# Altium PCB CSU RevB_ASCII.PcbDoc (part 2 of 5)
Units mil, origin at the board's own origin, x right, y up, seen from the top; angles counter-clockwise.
Board outline 5905.51 x 4330.71 mil, 8 copper layers (Top Layer, InternalPlane1, MidLayer1, InternalPlane2, MidLayer2, InternalPlane3, MidLayer3, Bottom Layer); 265 components, 387 nets, 1910 pads, 1151 vias.
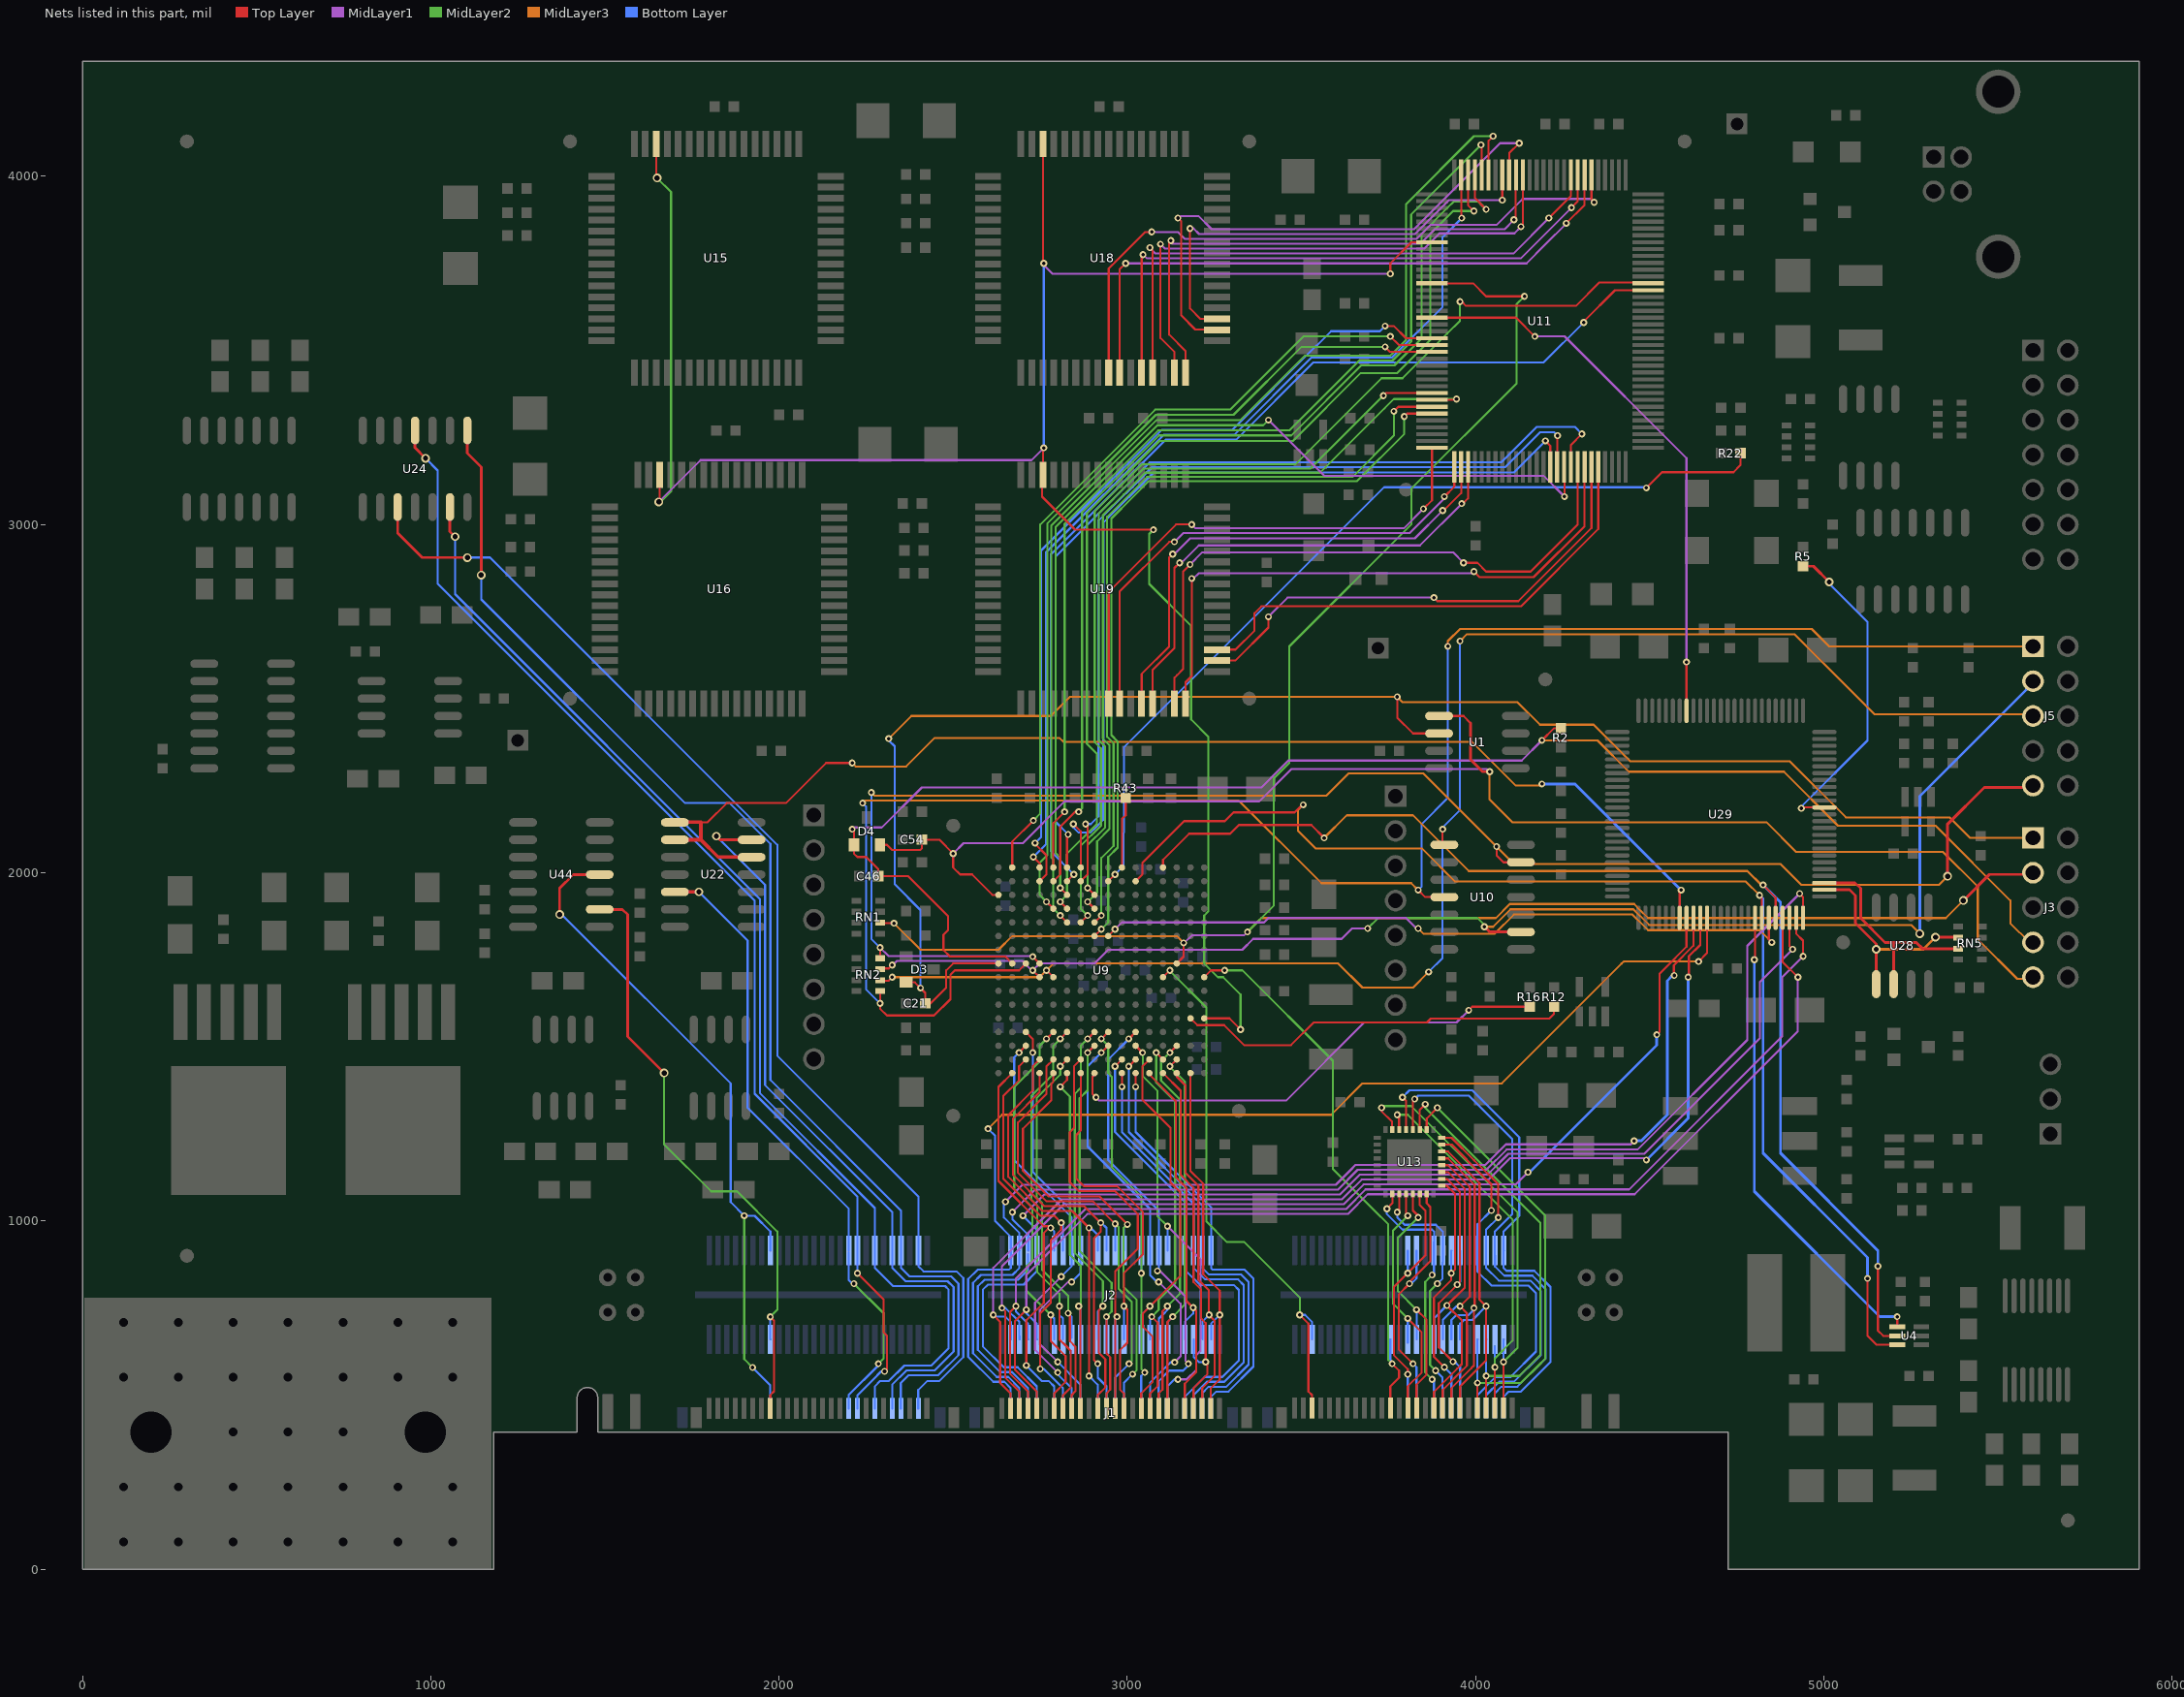
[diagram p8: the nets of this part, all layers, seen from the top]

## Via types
v1: diameter 20, hole 10, Top Layer to Bottom Layer, 647 vias
v2: diameter 25, hole 15, Top Layer to Bottom Layer, 352 vias
v3: diameter 20, hole 10, Top Layer to Bottom Layer, tented top, 151 vias
v4: diameter 20, hole 10, Top Layer to Bottom Layer, tented bottom, 1 vias

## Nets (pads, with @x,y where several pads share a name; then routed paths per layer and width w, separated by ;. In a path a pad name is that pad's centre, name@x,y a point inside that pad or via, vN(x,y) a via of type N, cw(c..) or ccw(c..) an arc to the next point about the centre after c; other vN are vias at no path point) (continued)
A_INP_SEL_N: U22.5 U22.8 U22.9 U29.57 | length 3570.2
  Top Layer w6: 1775,2145 1795,2145 1850,2200 2020,2200 2135,2315 v1(2210,2315) ; U29.57@4585.67,1870.51 4585.67,1945.67 v1(4590,1950)
  Top Layer w10: U22.8@1695,2150 1700,2145 1775,2145 1775.43,2144.57 1775.43,2094.57 ; U22.9@1701.14,2094.57 1775.43,2094.57 ; U22.5@1915,2045 1825,2045 1775.43,2094.57
  Top Layer w20: U22.5@1915,2045 U22.5@1925,2045
  MidLayer3 w6: v1(2210,2315) 2220,2305 2365,2305 2447.28,2387.28 2805,2387.28 2816.28,2376 3989,2376 4013.37,2351.63 4115,2250 4190,2250 v1(4190,2255)
  Bottom Layer w8: v1(4190,2255) 4285,2255 v1(4590,1950)
A_INTERFACE_RESET_N: J1.141 J2.141 U44.2 | length 1808.8
  Top Layer w6: J1.141@1974.71,461.79 J1.141@1974.71,470 ; v1(1974.71,724.71) 1985.71,713.71 1985.71,511 1975,500.29 J1.141@1975,470
  Top Layer w8: U44.2@1484.96,1894.57 1550.43,1894.57 1565,1880 1565,1530 v2(1670,1425)
  MidLayer2 w6: v2(1670,1425) 1670,1220 1805,1085 1880,1085 1995,970 1995,745 v1(1974.71,724.71)
  Bottom Layer w6: v1(1974.71,724.71) 1974.71,660.33 J2.141@1975.2,659.84
A_SCLK: J1.108 J2.108 U24.3 | length 3504.7
  Top Layer w8: U24.3@905,3050 905,2975 975,2905 v2(1105,2905)
  Bottom Layer w6: v2(1105,2905) 1170,2905 1995,2080 1995,1475 2400.2,1069.8 2400.2,869.8 2415,855 2510,855 2529,836 2529,609.2 2459.8,540 2425,540 2399.71,514.71 J1.108@2399.71,461.79
A_SIMO: J1.112 J2.112 U24.8 | length 3655.8
  Top Layer w8: U24.8@1105,3270 1105,3205 1145,3165 v2(1145,2855)
  Bottom Layer w6: v2(1145,2855) 1145,2785 1730,2200 1858.03,2200 1888.62,2169.41 1975,2083.03 1975,1405 2350.2,1029.8 2350.2,865 2374.2,841 2494,841 2515,820 2515,615 2457,557 2371.8,557 2349.71,534.91 J1.112@2349.71,461.79
A_SOMI: J1.114 J2.114 U22.6 | length 2222
  Top Layer w8: v2(1820,2105) 1830.43,2094.57 U22.6@1921.14,2094.57
  Bottom Layer w6: v2(1820,2105) 1960,1965 1960,1390 2325.2,1024.8 2325.2,865 2363.2,827 2484,827 2501,810 2501,625 2447,571 2366,571 2324.71,529.71 J1.114@2324.71,461.79
A_TCK: J5.1 RN2.1 U9.H3 U10.11 | length 5428.7
  Top Layer w6: RN2.1@2290.01,1660 2290.01,1635 v1(2290,1625) 2290.01,1609.99 2310,1590 2445,1590 2492,1637 2492,1707 2504.72,1719.72 2689.06,1719.72 U9.H3@2708.74,1739.41 ; v1(3835,1950) 3855,1930 U10.11@3910,1930
  MidLayer3 w6: v1(2240,2200) 2247,2207 3320,2207 3557,1970 3815,1970 v1(3835,1950) ; v1(3920,2650) 3920,2665 3955,2700 4965,2700 5015,2650 J5.1@5600,2650
  Bottom Layer w6: v1(2240,2200) 2249.7,2190.3 2249.7,1665.3 v1(2290,1625) ; v1(3835,1950) 3845,1960 3845,2140 3920,2215 v1(3920,2650)
A_TDI: J5.9 RN2.4 U9.H4 U10.6 | length 4774.8
  Top Layer w6: RN2.4@2290.01,1754.49 v1@2290.01,1784.99 ; v3(2728.43,1759.09) U9.H4@2748.11,1739.41 ; v1(4060,2075) 4060,2050 4080,2030 U10.6@4130,2030 U10.6@4135,2030
  Top Layer w8: v2(5355,1990) 5355,2140 5460,2245 5595,2245 J5.9@5600,2250
  MidLayer1 w6: v1(2290,1785) 2313.91,1761.09 2726.43,1761.09 v3(2728.43,1759.09)
  MidLayer3 w6: v1(2265,2230) 2274,2221 3571,2221 3635,2285 3850,2285 v1(4060,2075) 4110,2025 4875,2025 4935,1965 5330,1965 v2(5355,1990)
  Bottom Layer w6: v1(2265,2230) 2265,1810 v1(2290,1785)
A_TDO: J5.3 RN2.3 U9.J4 U10.2 | length 4126.9
  Top Layer w6: RN2.3@2290.01,1725 2315,1725 v1(2325,1735) ; v3(2728.43,1719.72) U9.J4@2748.11,1700.04
  Top Layer w8: v1(4025,1845) 4040,1830 U10.2@4130,1830
  MidLayer1 w6: v1@2326.97,1735 2339.07,1747.09 2697.91,1747.09 2725.28,1719.72 v3(2728.43,1719.72) ; v3@2729.72,1719.72 2729.72,1721.02 2748.11,1739.41 2905.59,1739.41 2944.96,1778.78 3330,1778.78 3361.22,1810 3615,1810 3645,1840 v1(3690,1840)
  MidLayer2 w6: v1(3690,1840) 3720,1870 4005,1870 4025,1850 v1(4025,1845)
  MidLayer3 w6: v1(4025,1845) 4050,1845 4100,1895 4453.03,1895 4498.03,1850 5250,1850 v2(5275,1825)
  Bottom Layer w8: v2(5275,1825) 5275,2220 5595,2540 5595,2545 J5.3@5600,2550
A_TMS: J5.5 RN2.2 U9.J5 U10.8 | length 4455.7
  Top Layer w6: RN2.2@2290,1690 2315,1690 v1(2325,1700) ; v3(2767.8,1719.72) U9.J5@2787.48,1700.04 ; v1(3905,2125) 3905,2085 U10.8@3910,2080
  MidLayer3 w6: v1(2325,1700) 2459.96,1700 2460,1700.04 2748.11,1700.04 v3(2767.8,1719.72) 2787.48,1739.41 3605.59,1739.41 3675,1670 3820,1670 v1(3865,1715) ; v1(3955,2665) 3975,2685 4915,2685 5145,2455 5595,2455 J5.5@5600,2460
  Bottom Layer w6: v1(3865,1715) 3905,1755 3905,2130 3955,2180 v1(3955,2665)
ADC_1_DAT0: J1.55 J2.55 U9.T15 | length 1088.2
  Top Layer w6: U9.T15@3181.18,1424.45 3181.18,1143.82 3218,1107 3218,847 3265,800 3265,545 3239.86,519.86 J1.55@3239.86,461.79
  Bottom Layer w6: J2.55@3240.35,659.84 3240.35,705.35 v1(3265,730)
ADC_1_DAT1: J1.57 J2.57 U9.T14 | length 1101.2
  Top Layer w6: U9.T14@3141.81,1424.45 3141.81,1414.37 3167.18,1389 3167.18,1138.02 3204,1101.2 3204,831 3234.02,800.98 3234.02,730 3251,713.02 3251,556 3215,520 3215,461.93 J1.57@3214.86,461.79
  Bottom Layer w6: J2.57@3215.35,659.84 3215.35,710.35 v1(3235,730)
ADC_1_DAT2: J1.59 J2.59 U9.T13 | length 1128
  Top Layer w6: U9.T13@3102.44,1424.45 3153.18,1373.71 3153.18,1132.02 3190,1095.2 3190,825 3211.86,803.14 3211.86,720 3225,706.86 v1(3225,595) ; J1.59@3189.86,461.79 3189.86,519.86 3230,560 3230,595 v1@3225,600
  Bottom Layer w6: J2.59@3190.35,659.84 3190.35,609.65 3205,595 v1(3225,595)
ADC_1_DAT3: J1.61 J2.61 U9.T12 | length 1133.1
  Top Layer w6: U9.T12@3063.07,1424.45 3063.07,1420.11 3139.18,1344 3139.18,1125.82 3170,1095 3170,770 3197.86,742.14 3197.86,566 3164.86,533 J1.61@3164.86,461.79
  Bottom Layer w6: J2.61@3165.35,659.84 3165.35,710.58 3189,734.22 v1(3189,751)
ADC_1_DAT4: J1.65 J2.65 U9.R14 | length 1120.9
  Top Layer w6: J1.65@3114.86,461.79 3114.86,709.86 v1(3130,725) ; v3(3122.13,1444.13) U9.R14@3141.81,1463.82
  MidLayer2 w6: v3(3122.13,1444.13) 3122.13,1442.87 3165,1400 3165,760 v1(3130,725)
  Bottom Layer w6: J2.65@3115.35,659.84 3115,659.49 3115,710 v1(3130,725)
ADC_1_DAT5: J1.67 J2.67 U9.P14 | length 1213.4
  Top Layer w6: J1.67@3089.86,461.79 3089.86,505 3100.86,516 3100.86,740.86 v1(3115,755) ; v3(3122.13,1483.5) U9.P14@3141.81,1503.19
  MidLayer2 w6: v1(3115,755) 3151,791 3151,1348.76 3096.76,1403 3096.76,1458.13 v3(3122.13,1483.5)
  Bottom Layer w6: J2.67@3090.35,659.84 3090.35,719.83 3103.15,732.63 ; 3103.03,732.51 3115,744.48 v1(3115,755)
ADC_1_DAT6: J1.69 J2.69 U9.R13 | length 1183.2
  Top Layer w6: J1.69@3064.86,461.79 3064.86,504 3086.86,526 3086.86,708.14 v1(3070,725) ; v3(3082.76,1483.5) U9.R13@3102.44,1463.82
  MidLayer2 w6: v1(3070,725) 3090,745 3090,774 3137,821 3137,1342.96 3082.76,1397.2 v3(3082.76,1483.5)
  Bottom Layer w6: J2.69@3065.35,659.84 3065,660.2 3065,715 3070,720 v1(3070,725)
ADC_1_DAT7: J1.71 J2.71 U9.R12 | length 1219.6
  Top Layer w6: J1.71@3039.86,461.79 3039.86,504.86 3072.86,537.86 3072.86,667.14 3045,695 3045,735 3151.48,841.48 3151.48,1083.52 3124,1111 3124,1267 3043.39,1347.61 3043.39,1444.13 U9.R12@3063.07,1463.82
  Bottom Layer w6: J2.71@3040,670 3040,730 v1(3065,755)
ADC_2_DAT0: J1.56 J2.56 U9.T11 | length 1227.8
  Top Layer w6: v1(3023.7,1385.08) U9.T11@3023.7,1424.45
  Bottom Layer w6: v1(3023.7,1385.08) 3023.7,1255.7 3240.35,1039.04 J2.56@3240.35,914.96 3240.35,864.65 3245,860 3337,860 3362,835 3362,582 3290,510 3255,510 3239.86,494.86 J1.56@3239.86,461.79
ADC_2_DAT1: J1.58 J2.58 U9.R11 | length 1291.7
  Top Layer w6: v3(3004.02,1444.13) U9.R11@3023.7,1463.82
  Bottom Layer w6: v3(3004.02,1444.13) 3004.02,1424.45 3004.02,1255.58 3215.35,1044.24 3215.35,932.32 3215.35,865 3234.35,846 3327,846 3348,825 3348,587.8 3284.2,524 3233.6,524 3214.86,505.27 J1.58@3214.86,461.79
ADC_2_DAT2: J1.60 J2.60 U9.T10 | length 1252.3
  Top Layer w6: v1(2984.33,1385.08) U9.T10@2984.33,1424.45
  Bottom Layer w6: v1(2984.33,1385.08) 2984.33,1255.47 3030.17,1209.62 3190.35,1049.44 J2.60@3190.35,914.96 3190.35,865 3223.35,832 3318,832 3334,816 3334,593.6 3278.4,538 3227.8,538 3189.86,500.06 J1.60@3189.86,461.79
ADC_2_DAT3: J1.62 J2.62 U9.R10 | length 1307.9
  Top Layer w6: v3(2964.65,1444.13) U9.R10@2984.33,1463.82
  Bottom Layer w6: v3(2964.65,1444.13) 2964.65,1255.35 3018.78,1201.22 3165,1055 3165,915.31 J2.62@3165.35,914.96 ; J1.62@3164.86,461.79 3164.86,494.86 3222,552 3272.6,552 3320,599.4 3320,802 3305.85,816.15 3208.85,816.15 3165,860 J2.62@3165,914.61
ADC_2_DAT4: J1.66 J2.66 U9.P11 | length 1248.5
  Top Layer w6: U9.P11@3023.7,1503.19 v3(3043.39,1483.5)
  MidLayer1 w6: v1(3115.35,985) 3210,890.35 3210,627 3198,615 3198,572.99 3170,545 v1(3145,545)
  MidLayer2 w6: v3(3043.39,1483.5) 3045,1481.89 3045,1415.16 3086,1374.16 3086,1014.35 v1(3115.35,985)
  Bottom Layer w6: J1.66@3114.86,461.79 3114.86,524.86 3135,545 v1(3145,545) ; J2.66@3115.35,914.96 v1(3115.35,985)
ADC_2_DAT5: J1.68 J2.68 U9.N11 | length 1275
  Top Layer w6: v3(3004.02,1522.87) U9.N11@3023.7,1542.56
  MidLayer1 w6: v1(3086.35,856.35) 3093.65,856.35 3166.85,783.15 3166.85,598.15 v1(3175,590)
  Bottom Layer w6: v3(3004.02,1522.87) 2944.96,1463.82 2944.96,1174.64 2977.72,1141.88 3090.35,1029.24 3090.35,932.32 3090.35,860.35 v1(3086.35,856.35) ; J1.68@3089.86,461.79 3089.86,539.86 3110.18,560.18 3120,570 3160,570 3175,585 v1(3175,590)
ADC_2_DAT6: J1.70 J2.70 U9.P9 | length 1228.5
  Top Layer w6: v3(2925.28,1483.5) U9.P9@2944.96,1503.19 ; v1(3135.86,594.14) v1@3140,590
  MidLayer1 w6: v1(3089.94,825) 3090,825 3142.81,772.19 3152.85,762.15 3152.85,611.12 v1(3135.86,594.14)
  Bottom Layer w6: v3(2925.28,1483.5) 2885.91,1444.13 2885.91,1213.89 2950.11,1149.69 3065.35,1034.44 3065.35,912.64 3065.35,844.65 3085,825 v1(3089.94,825) ; J1.70@3064.86,461.79 3064.86,495 3065,495.14 3065,535 3108.36,578.36 3124.14,594.14 v1(3135.86,594.14)
ADC_2_DAT7: J1.72 J2.72 U9.N9 | length 1209.7
  Top Layer w6: v3(2925.28,1522.87) U9.N9@2944.96,1542.56
  MidLayer2 w6: v3(2925.28,1522.87) 2944.96,1503.19 2944.96,1424.45 2955.13,1414.28 2955.13,1154.98 3040,1070.12 v1(3040,850) 3040.9,849.1 3040.9,574.1 v1(3050,565)
  Bottom Layer w6: J1.72@3039.86,461.79 3039.86,554.86 v1(3050,565) ; v1(3040,850) J2.72@3040,914.96
ADC_3_DAT0: J1.75 J2.75 U9.T7 | length 1237.5
  Top Layer w6: U9.T7@2866.22,1424.45 2866.22,1259.5 2854,1247.28 2854,1121 2875,1100 2970,1100 3045,1025 3045,905 2990,850 v1(2990,755) 3000,745 3000,650 2978.86,628.86 2978.86,516.14 2989.86,505.14 J1.75@2989.86,461.79
  Bottom Layer w6: J2.75@2990.35,659.84 v1@2990.35,754.65
ADC_3_DAT1: J1.77 J2.77 U9.R7 | length 1262.8
  Top Layer w6: U9.R7@2866.22,1463.82 2846.54,1444.13 2846.54,1266.54 2835,1255 2835,1111 2860,1086 2964,1086 3030,1020 3030,920 2964.86,854.86 J1.77@2964.86,461.79 ; 2964.86,735 2970,729.86 v1(2970,725)
  Bottom Layer w6: J2.77@2965.35,659.84 2965.35,720.35 v1(2970,725)
ADC_3_DAT2: J1.79 J2.79 U9.P8 | length 1177.7
  Top Layer w6: v3(2885.91,1483.5) U9.P8@2905.59,1503.19 ; J1.79@2939.86,461.79 2939.86,480 2940,480.14 2940,505.14 2950.86,516 2950.86,608.73 2940,619.6 v1(2940,725)
  MidLayer2 w6: v3(2885.91,1483.5) 2885.91,1375 2863,1352.09 2863,914.03 2955,822.03 2955,740 v1(2940,725)
  Bottom Layer w6: v1(2940,725) 2940.35,724.65 J2.79@2940.35,659.84
ADC_3_DAT3: J1.81 J2.81 U9.N8 | length 1260.9
  Top Layer w6: v3(2885.91,1522.87) U9.N8@2905.59,1542.56 ; J1.81@2914.86,461.79 2914.86,499.86 2936.86,521.86 2936.86,602.94 2918,621.8 2918,743 v1(2930,755)
  MidLayer2 w6: v3(2885.91,1522.87) 2866.22,1503.19 2866.22,1382.22 2849,1365 2849,908.23 2930,827.23 v1(2930,755)
  Bottom Layer w6: J2.81@2915.35,659.84 2915.35,740.35 v1(2930,755)
ADC_3_DAT4: J1.85 J2.85 U9.T6 | length 1097.7
  Top Layer w6: v1(2807.17,1385.08) 2826.85,1404.76 U9.T6@2826.85,1424.45 ; v1(2860,755) 2865,750 2865,510 ; J1.85@2864.86,461.79 2864.86,510
  MidLayer2 w6: v1(2807.17,1385.08) 2835,1357.24 2835,902.43 2866.22,871.21 2866.22,761.22 v1(2860,755)
  Bottom Layer w6: v1(2860,755) 2865,750 2865,660.2 J2.85@2865.35,659.84 J2.85@2865.35,660.2
ADC_3_DAT5: J1.87 J2.87 U9.R6 | length 1164.5
  Top Layer w6: v3(2807.17,1444.13) U9.R6@2826.85,1463.82 ; v1(2830,735) 2835,730 2835,655 2850.86,639.14 2850.86,510.86 2840,500 J1.87@2840,460 ; J1.87@2839.86,461.79 J1.87@2840,461.93
  MidLayer2 w6: v3(2807.17,1444.13) 2807.17,1420.59 2740,1353.42 2740,1066.6 2755,1051.6 2755,860 2830,785 v1(2830,735)
  Bottom Layer w6: v1(2830,735) 2840,725 J2.87@2840,665
ADC_3_DAT6: J1.89 J2.89 U9.N6 | length 1278.4
  Top Layer w6: v1(2805,755) 2805,660 2824.55,640.45 2836.86,628.14 2836.86,521 2814.86,499 J1.89@2814.86,461.79 ; v3(2807.17,1522.87) U9.N6@2826.85,1542.56
  MidLayer2 w6: v1(2805,755) 2805,790 2741,854 2741,1045.8 2725,1061.8 2725,1360 2787.48,1422.48 2787.48,1503.19 v3(2807.17,1522.87)
  Bottom Layer w6: v1(2805,755) 2805,730 2815.35,719.65 J2.89@2815.35,659.84 J2.89@2815,660.2
ADC_3_DAT7: J1.91 J2.91 U9.N5 | length 1290.6
  Top Layer w6: v3(2767.8,1522.87) U9.N5@2787.48,1542.56 ; v1(2780,730) 2780,655 2822.86,612.14 2822.86,537.86 2789.86,504.86 J1.91@2789.86,461.79
  MidLayer2 w6: v3(2767.8,1522.87) 2748.11,1503.19 2748.11,1458.11 2675,1385 2675,1092 2727,1040 2727,886 2710.69,869.69 2710.69,799.31 v1(2780,730)
  Bottom Layer w6: v1(2780,730) 2790,720 J2.91@2790,660 ; J2.91@2790,660.2 J2.91@2790.35,659.84 J2.91@2790.35,660
ADC_4_DAT0: J1.76 J2.76 U9.T5 | length 1323.5
  Top Layer w6: U9.T5@2787.48,1424.45 2787.48,1399.68 2781.8,1394 2781.8,1346.8 2700,1265 2700,1143.99 2773.2,1070.8 2919.56,1070.8 3000,990.35 v1(3000,990)
  MidLayer2 w6: v1(3000,990) 2989,979 2989,811 3026.9,773.1 3026.9,571.9 v1(3015,560)
  Bottom Layer w6: J1.76@2989.86,461.79 2989.86,534.86 v1(3015,560) ; J2.76@2990.35,914.96 2990.35,980.35 v1(3000,990)
ADC_4_DAT1: J1.78 J2.78 U9.R5 | length 1354.2
  Top Layer w6: U9.R5@2787.48,1463.82 2767.8,1444.13 2767.8,1364.56 2686,1282.77 2686,1138.2 2767.4,1056.8 2900.2,1056.8 v1(2965,992)
  MidLayer2 w6: v1(2965,992) 2975,982 2975,805 3012.9,767.1 3012.9,597.9 v1(3005,590)
  Bottom Layer w6: J1.78@2964.86,461.79 2964.86,549.86 v1(3005,590) ; J2.78@2965,920 v1(2965,992) ; J2.78@2965.35,914.96 J2.78@2965.35,920
ADC_4_DAT2: J1.80 J2.80 U9.T4 | length 1266.3
  Top Layer w6: U9.T4@2748.11,1424.45 2748.11,1370.11 2672,1294 2672,1132.4 2761.6,1042.8 2875.74,1042.8 v1(2923.54,995) 2923.54,969.54 2904,950 2904,601 v1(2915,590)
  Bottom Layer w6: v1(2915,590) 2915,549.8 2940,524.8 J1.80@2940,470 ; v1@2925.35,995 2940.35,980 J2.80@2940.35,914.96
ADC_4_DAT3: J1.82 J2.82 U9.R4 | length 1274.2
  Top Layer w6: U9.R4@2748.11,1463.82 2728.43,1444.13 2728.43,1374.43 2658,1304 2658,1126.6 2755.8,1028.8 2841.2,1028.8 v1(2890,980) v1(2890,555)
  Bottom Layer w6: v1(2890,555) 2914.86,530.14 J1.82@2914.86,461.79 ; v1(2890,980) 2895,975 2900,975 2915.35,959.65 J2.82@2915.35,914.96
ADC_4_DAT4: J1.86 J2.86 U9.N3 | length 1247.7
  Top Layer w6: U9.N3@2708.74,1542.56 2728.43,1522.87 v3(2728.43,1483.5)
  MidLayer1 w6: v1(2800,595) 2749,646 2749,744 2830,825 v1(2840,825)
  Bottom Layer w6: v3(2728.43,1483.5) 2728.43,1141.18 2773.1,1096.5 2865.35,1004.25 2865.35,912.64 2865.35,850.35 v1(2840,825) ; v1(2800,595) 2864.86,530.14 J1.86@2864.86,461.79
ADC_4_DAT5: J1.88 J2.88 U9.P3 | length 1218.3
  Top Layer w6: v3(2689.06,1483.5) U9.P3@2708.74,1503.19
  MidLayer1 w6: v1(2800,565) 2735,630 2735,765 v4(2810,840)
  Bottom Layer w6: v3(2689.06,1483.5) 2688.5,1483.5 2675,1470 2675,1174.8 2714.75,1135.05 2840.35,1009.45 2840.35,912.64 2840.35,870.35 v4(2810,840) ; v1(2800,565) 2795,565 2839.86,520.14 J1.88@2839.86,461.79
ADC_4_DAT6: J1.90 J2.90 U9.R3 | length 1261
  Top Layer w6: U9.R3@2708.74,1463.82 2689.06,1444.13 2689.06,1404.06 2644,1359 2644,1120.8 2750,1014.8 2790.2,1014.8 v1(2810,995) 2810,975 2800,965 ; v1(2750,575) 2750,735.2 2780,765.2 2780,944.65 2800.18,964.82
  Bottom Layer w6: v1(2750,575) 2760,575 2815,520 2815,475.14 2814.86,475 J1.90@2814.86,461.79 ; v1(2810,995) 2815.35,989.65 J2.90@2815.35,914.96
ADC_4_DAT7: J1.92 J2.92 U9.T2 | length 1198.6
  Top Layer w6: U9.T2@2669.41,1424.41 U9.T2@2670,1425 ; U9.T2@2669.37,1424.45 2630,1385.08 2630,1115 2760,985 v1@2780,985 ; v1(2710,585) 2710,715 2760,765 2760,965 v1@2780,985 ; v1(2780,980) v1@2780,985
  Bottom Layer w6: v1(2710,585) 2755,540 2775,540 2790,525 J1.92@2790,465 ; v1(2780,980) 2790.35,969.65 J2.92@2790.35,914.96
ADDR0: U9.C8 U11.94 | length 2231.9
  Top Layer w6: v3(2885.91,1955.94) U9.C8@2905.59,1936.26 ; v1(3735,3370) 3742.48,3377.48 U11.94@3874.45,3377.48
  MidLayer2 w6: v3(2885.91,1955.94) 2885.91,2079.63 2936.33,2130.06 2936.33,2361.82 2918,2380.15 2918,3031.97 3006.75,3120.72 3046.6,3160.57 3525.57,3160.57 v1(3735,3370)
ADDR1: U9.D8 U11.95 | length 2396.7
  Top Layer w6: v3(2885.91,1916.57) U9.D8@2905.59,1896.89 ; U11.95@3874.45,3357.8 3942.8,3357.8 v1(3945,3360)
  MidLayer2 w6: v3(2885.91,1916.57) 2886.85,1916.57 2913.28,1943 2913.28,2090.03 2948.33,2125.09 2948.33,2366.79 2930,2385.12 2930,3027 2989.45,3086.45 3051.57,3148.57 3553.57,3148.57 3738.55,3333.55 3765,3360 v1(3945,3360)
ADDR2: U9.E8 U11.96 | length 2299.2
  Top Layer w6: U9.E8@2905.59,1857.52 v3(2925.28,1877.2) ; v1(3765,3325) 3778.11,3338.11 U11.96@3874.45,3338.11
  MidLayer2 w6: v3(2925.28,1877.2) 2925.28,2042.29 2960.33,2077.34 2960.33,2371.76 2942,2390.09 2942,3022.03 3056.54,3136.57 3646.57,3136.57 3765,3255 v1(3765,3325)
ADDR3: U9.F8 U11.97 | length 2308.7
  Top Layer w6: U9.F8@2905.59,1818.15 v3(2925.28,1837.83) ; v1(3795,3310) 3803.43,3318.43 U11.97@3874.45,3318.43
  MidLayer2 w6: v3(2925.28,1837.83) 2944.96,1857.52 2944.96,2045 2972.33,2072.37 2972.33,2376.73 2954,2395.06 2954,3017.06 3015.01,3078.07 3061.51,3124.57 3659.57,3124.57 3795,3260 v1(3795,3310)
ADDR4: U9.A7 U11.117 | length 2551
  Top Layer w6: v1(2845,2140) 2866.22,2118.78 U9.A7@2866.22,2015 ; v1(4200,3240) 4214.25,3225.75 U11.117@4214.25,3165.63
  Bottom Layer w6: v1(2845,2140) 2845,2130 2860,2115 2894,2115 2908.52,2129.52 2931.16,2152.16 2931.16,3005.27 3075,3149.11 4109.11,3149.11 v1(4200,3240)
ADDR5: U9.B7 U11.118 | length 2587.2
  Top Layer w6: U9.B7@2866.22,1975.63 2885.91,1995.32 2885.91,2134.09 v1(2880,2140) ; U11.118@4233.94,3165.63 4233.94,3253.94 v1(4235,3255)
  Bottom Layer w6: v1(2880,2140) 2895,2140 2917.16,2162.16 2917.16,3011.07 3070.8,3164.71 4084.71,3164.71 4185,3265 4225,3265 v1(4235,3255)
ADDR6: U9.C6 U11.119 | length 2835.7
  Top Layer w6: v3(2807.17,1955.94) U9.C6@2826.85,1936.26 ; U11.119@4253.62,3165.63 4255,3164.25 v1(4255,3080)
  MidLayer1 w6: v1(3405,3300) 3565,3140 4195,3140 v1(4255,3080)
  MidLayer2 w6: v3(2807.17,1955.94) 2807.17,2042.83 2794,2056 2794,2992.82 3086.18,3285 3390,3285 v1(3405,3300)
ADDR7: U9.A6 U11.120 | length 2689.6
  Top Layer w6: U9.A6@2826.85,2015 2826.85,2106.85 v1(2830,2110) ; U11.120@4273.31,3165.63 4273.31,3228.31 v1(4305,3260)
  Bottom Layer w6: v1(2830,2110) 2830,2110.35 2794.35,2146 2794.35,2908.06 3065,3178.71 4073.71,3178.71 4175,3280 4285,3280 v1(4305,3260)
ADDR14: U9.B6 U11.24 | length 3004.4
  Top Layer w6: U9.B6@2826.85,1975.63 v3(2846.53,1995.32) ; v1(4310,3580) 4310,3582.76 4400,3672.76 U11.24@4495,3672.76
  Bottom Layer w6: v3(2846.53,1995.32) 2780.35,2061.5 2780.35,2913.86 3110,3243.51 3312.4,3243.51 3533.89,3465 4195,3465 v1(4310,3580)
ADDR15: U9.E7 U11.25 | length 3126.4
  Top Layer w6: U9.E7@2866.22,1857.52 v3(2885.91,1877.2) ; v1(3955,3640) 3960,3640 3972.3,3627.7 4287.7,3627.7 4355,3695 U11.25@4490,3695
  MidLayer2 w6: v3(2885.91,1877.2) 2866.22,1896.89 2866.22,2076.92 2924.33,2135.03 2924.33,2356.85 2906,2375.18 2906,3036.94 3041.63,3172.57 3482.57,3172.57 3730,3420 3790,3420 3917.89,3547.89 3955,3585 v1(3955,3640)
ASD: C54.1 D4.2 J3.9 U1.5 U9.C1 | length 4323.5
  Top Layer w6: D4.2@2289.8,2080 2310,2080 2325,2065 2405,2065 2410,2070 C54.1@2410,2095.01 2459.99,2095.01 v1(2500,2055) 2500,2015 2520,1995 2553.97,1995 2612.71,1936.26 U9.C1@2630,1936.26 ; U1.5@3895,2450 3965,2450 3985,2430
  Top Layer w8: 3985,2430 3985,2325 4020,2290 v1(4040,2290)
  MidLayer1 w6: v1(2500,2055) 2529.75,2084.75 2699.75,2084.75 2820,2205 3378.94,2205 3471.94,2298 4032,2298 v1(4040,2290)
  MidLayer3 w6: v1(4040,2290) 4040,2210 4105,2145 4835,2145 4920,2060 5341.48,2060 5441.48,1960 5441.48,1808.52 5555,1695 5595,1695 J3.9@5600,1700
ASP_1_SEL_N: J1.95 J2.95 U29.72 | length 3369.2
  Top Layer w6: v1(2710,745) 2677,712 2677,573 2739.86,510.14 J1.95@2739.86,461.79 ; U29.72@4880.94,1870.51 4880.94,1744.06 v1(4925,1700)
  MidLayer1 w6: v1(2710,745) 2710,845 2885,1020 3633.25,1020 3690,1076.75 4456.75,1076.75 4925,1545 v1(4925,1700)
  Bottom Layer w6: v1(2710,745) 2710,735 2740,705 J2.95@2740,660 ; J2.95@2740.35,659.84 J2.95@2740.35,660
ASP_2_SEL_N: J1.96 J2.96 U29.73 | length 3497.3
  Top Layer w6: U29.73@4900.63,1870.51 4900.63,1789.37 v1(4910,1780)
  MidLayer1 w6: v1(2700,1015) 2761,1076 3610.06,1076 3622.2,1088.14 3666.8,1132.75 4033.59,1132.75 4093.84,1193 4483.92,1193 4815.92,1525 4815.92,1685.92 v1(4910,1780)
  Bottom Layer w6: v1(2700,1015) 2740.35,974.65 J2.96@2740.35,914.96 2740,914.61 2740,855 2702.2,817.2 2600,817.2 2585,802.2 2585,640 2645,580 2685,580 2739.86,525.14 J1.96@2739.86,461.79
ASP_3_SEL_N: J1.97 J2.97 U29.74 | length 3377.4
  Top Layer w6: v1(2680,755) 2663,738 2663,562 2714.86,510.14 J1.97@2714.86,461.79 ; U29.74@4920,1875 4920,1825 4940,1805 v1(4940,1760)
  MidLayer1 w6: v1(2680,755) 2680,834.8 2879.2,1034 3627.45,1034 3684.2,1090.75 4440.75,1090.75 4880,1530 4880,1700 v1(4940,1760)
  Bottom Layer w6: v1(2680,755) 2680,740 2715,705 2715,660.2 J2.97@2715.35,659.84
ASP_4_SEL_N: J1.98 J2.98 U29.75 | length 3638.3
  Top Layer w6: v1(4930,1940) 4940,1930 U29.75@4940,1870.51
  MidLayer1 w6: v1(2670,1025) 2735,1090 3604.26,1090 3661,1146.75 4030.62,1146.75 4088.87,1205 4465,1205 4780,1520 4780,1790 v1(4930,1940)
  Bottom Layer w6: v1(2670,1025) 2670,1005 2715.35,959.65 J2.98@2715.35,914.96 ; J1.98@2714.86,461.79 2714.86,520 2668.86,566 2635,566 2571,630 2571,812.2 2590,831.2 2686.2,831.2 2715,860 J2.98@2715,905
ATTN: U11.83 U29.18 | length 1624
  Top Layer w6: U11.83@3874.45,3594.02 4115.98,3594.02 v1(4170,3540) ; U29.18@4605,2465 U29.18@4605.35,2465 4605.35,2604.65 v1(4605,2605)
  MidLayer1 w6: v1(4170,3540) 4170.4,3540.4 4255,3540.4 4605,3190.4 v1(4605,2605)
B2_SCLK: U4.2 U9.A13 U29.71 | length 3514.5
  Top Layer w6: U9.A13@3102.44,2015 3102.44,2036.86 3177.58,2112 3294.88,2112 3319.88,2137 3528,2137 v1(3565,2100) ; v1(4825,1965) 4861.26,1928.74 U29.71@4861.26,1855 ; v1(5155,870) 5155,685 5170,670 U4.2@5210.55,670
  MidLayer3 w6: v1(3565,2100) 3630,2165 3820,2165 3980,2005 4780,2005 4820,1965 v1(4825,1965)
  Bottom Layer w8: v1(4825,1965) 4875,1915 4875,1195 5155,915 v1(5155,870)
B2_SIMO: U4.3 U9.B11 U29.69 | length 3642
  Top Layer w6: U9.B11@3023.7,1975.63 3043.39,1995.32 3043.39,2028.71 3162.67,2148 3279.97,2148 3304.97,2173 3480,2173 3502,2195 v1(3505,2195) ; v1(4815,1935) 4821.89,1928.11 U29.69@4821.89,1860 ; v1(5125,835) 5125,670 5150.59,644.41 U4.3@5210.55,644.41
  MidLayer3 w6: v1(3505,2195) 3490,2180 3490,2120 3540,2070 3845,2070 3940,1975 4775,1975 v1(4815,1935)
  Bottom Layer w8: v1(4815,1935) 4825,1925 4825,1195 5125,895 v1(5125,835)
B2_SOMI: U9.F9 U29.70 | length 2075.1
  Top Layer w6: U9.F9@2944.96,1818.15 v3(2964.65,1837.83) ; U29.70@4841.57,1870.51 4841.57,1808.43 v1(4850,1800)
  MidLayer1 w6: v3(2964.65,1837.83) 2984.33,1857.52 3392.52,1857.52 3405,1870 3800,1870 3830,1840 v1(3835,1840)
  MidLayer3 w6: v1(3835,1840) 3850,1825 4055,1825 4110,1880 4450,1880 4495,1835 4815,1835 v1(4850,1800)
B3_SCL: RN5.3 U28.6 U29.78 | length 632
  Top Layer w8: U29.78@5001.02,1970.91 5089.09,1970.91 5105,1955 5105,1870 5175,1800 5265,1800 5282.99,1782.01 RN5.3@5384.99,1782.01 ; U28.6@5200,1680 5200,1800
B3_SDA: RN5.2 U28.5 U29.77 | length 625.7
  Top Layer w8: U29.77@5001.02,1951.22 5073.78,1951.22 5090,1935 5090,1855 5150,1795 v2(5150,1780) U28.5@5150,1680 ; v2(5320,1815) 5383.5,1815 RN5.2@5384.99,1813.5
  MidLayer3 w8: v2(5150,1780) 5285,1780 v2(5320,1815)
B_DAT0: U11.44 U18.25 | length 1878
  Top Layer w6: U18.25@2946.46,3436 2946.46,3735 3051.46,3840 v1(3070,3840) ; U11.44@4332.36,4003.72 4332.36,3932.64 v1(4340,3925)
  MidLayer1 w6: v1(3070,3840) 3145,3840 3165,3820 3830,3820 3870,3860 4060,3860 4135,3935 4330,3935 v1(4340,3925)
B_DAT1: U11.45 U18.26 | length 1794.8
  Top Layer w6: U18.26@2977.95,3436 2977.95,3732.95 v1(2995,3750) ; v1(4260,3865) 4312.68,3917.68 U11.45@4312.68,4003.72
  MidLayer1 w6: v1(2995,3750) 4146,3750 4199.2,3803.2 4260,3864 v1(4260,3865)
B_DAT2: U11.46 U18.28 | length 1736.9
  Top Layer w6: U18.28@3040.94,3436 3040.94,3765 3045,3769.06 v1(3045,3775) ; v1(4275,3910) 4292.99,3927.99 U11.46@4292.99,4003.72
  MidLayer1 w6: v1(3045,3775) 3056,3764 4129,3764 v1(4275,3910)
B_DAT3: U11.47 U18.29 | length 1706.9
  Top Layer w6: v1(3065,3795) 3072.44,3787.56 U18.29@3072.44,3436 ; v1(4210,3880) 4273.31,3943.31 U11.47@4273.31,4003.72
  MidLayer1 w6: v1(3065,3795) 3065,3794 3081,3778 4108,3778 v1(4210,3880)
B_DAT4: U11.54 U18.31 | length 1604
  Top Layer w6: v1(3095,3805) 3095,3535.43 3135.43,3495 U18.31@3135.43,3436 ; v1(4130,3855) 4135.51,3860.51 U11.54@4135.51,4003.72 U11.54@4135,4003.2
  MidLayer1 w6: v1(3095,3805) 3108,3792 3852,3792 3896,3836 4111,3836 v1(4130,3855)
B_DAT5: U11.55 U18.32 | length 1552.7
  Top Layer w6: v1@3120,3815 3120,3545 3166.93,3498.07 U18.32@3166.93,3436 ; v1(4110,3875) 4115,3880 4115,4002.89 U11.55@4115.83,4003.72 U11.55@4115.83,4002.89
  MidLayer1 w6: v1@3120,3815 3129,3806 3841,3806 3883,3848 4083,3848 v1(4110,3875)
  other v1: 3125,3815
B_DAT6: U11.56 U18.34 | length 1610.3
  Top Layer w6: v1(3145,3880) 3155,3870 3155,3600 3195,3560 U18.34@3260,3560 ; U11.56@4095,4004.86 U11.56@4096.14,4003.72 4096.14,4066.14 v1(4125,4095)
  MidLayer1 w6: v1(3145,3880) 3150,3885 3205,3885 3242,3848 3823,3848 4039.9,4064.9 4070,4095 v1(4125,4095)
B_DAT7: U11.57 U18.35 | length 1335.9
  Top Layer w6: v1(3180,3850) 3180,3620 3209.45,3590.55 U18.35@3258,3590.55 ; v1(4076.46,3931.46) U11.57@4076.46,4003.72
  MidLayer1 w6: v1(3180,3850) 3190,3850 3206,3834 3825.97,3834 3923.43,3931.46 v1(4076.46,3931.46)
B_DAT8: U11.102 U19.25 | length 1517
  Top Layer w6: U19.25@2946.46,2486 2946.46,2806.46 3140,3000 v1(3185,3000) ; v1(3850,3045) 3874.45,3069.45 U11.102@3874.45,3220
  MidLayer1 w6: v1(3185,3000) 3196,2989 3794,2989 v1(3850,3045)
B_DAT9: U11.103 U19.26 | length 1467.1
  Top Layer w6: U19.26@2977.95,2486 2977.95,2807.95 3120,2950 v1(3135,2950) ; v1(3910,3080) 3938.66,3108.66 U11.103@3938.66,3165.63
  MidLayer1 w6: v1(3135,2950) 3160,2975 3810,2975 3910,3075 v1(3910,3080)
B_DAT10: U11.104 U19.28 | length 1457.3
  Top Layer w6: U19.28@3040.94,2486 3040.94,2570.94 3120,2650 3120,2905 v1(3130,2915) ; v1(3905,3040) 3908.35,3040 3958.35,3090 3958.35,3176.65 U11.104@3955.57,3179.43
  MidLayer1 w6: v1(3130,2915) 3135,2915 3180,2960 3825,2960 v1(3905,3040)
B_DAT11: U11.105 U19.29 | length 1431.4
  Top Layer w6: U19.29@3072.44,2486 3072.44,2582.64 3135,2645.2 3135,2875 v1(3150,2890) ; v1(3960,3060) 3963.03,3060 3978.03,3075 U11.105@3978.03,3165.63
  MidLayer1 w6: v1(3150,2890) 3155,2890 3205,2940 3840,2940 v1(3960,3060)
B_DAT12: U11.121 U19.31 | length 1789.3
  Top Layer w6: U19.31@3135.43,2486 3135.43,2560.43 3142.38,2567.38 3160,2585 3160,2865 v1(3180,2885) ; v1(3965,2890) 4005,2890 4030,2865 4157.99,2865 4292.99,3000 U11.121@4292.99,3165.63
  MidLayer1 w6: v1(3180,2885) 3215,2920 3935,2920 v1(3965,2890)
B_DAT13: U11.122 U19.32 | length 1743.4
  Top Layer w6: U19.32@3166.93,2486 3166.93,2546.93 3185,2565 v1(3185,2845) ; v1(3995,2865) 4011.34,2848.66 4166.33,2848.66 4312.68,2995 U11.122@4312.68,3165.63
  MidLayer1 w6: v1(3185,2845) 3190,2845 3205,2860 v1@4000,2860
B_DAT14: U11.123 U19.34 | length 1434.2
  Top Layer w6: U19.34@3258,2609.06 3310,2609.06 3405,2704.06 v1(3405,2735) ; v1(3880,2790) 3890,2780 4122.36,2780 4332.36,2990 U11.123@4332.36,3165.63
  MidLayer1 w6: v1(3405,2735) 3460,2790 v1(3880,2790)
B_DAT15: U11.124 U19.35 | length 1445.4
  Top Layer w6: U19.35@3258,2640.55 3310.55,2640.55 3365,2695 3365,2745 3385,2765 4130,2765 4352.05,2987.05 U11.124@4352.05,3165.63
B_INTERFACE_RESET_N: J1.142 J2.142 U44.4 | length 2028.5
  Top Layer w8: v2(1370,1880) 1370,1955 1409.57,1994.57 U44.4@1484.96,1994.57
  MidLayer2 w6: v1(1900,1015) 1900,603.35 v1(1924.18,579.18) v1@1925,580
  Bottom Layer w6: v2(1370,1880) 1376,1880 1861,1395 1861,1054 v1(1900,1015) 1930,1015 1975.2,969.8 J2.142@1975.2,914.96 ; v1(1924.18,579.18) 1974.71,528.65 J1.142@1974.71,461.79
B_SCLK: J1.118 J2.118 U24.6 | length 3421.8
  Top Layer w8: U24.6@1055,3055 1055,2980 v2(1070,2965)
  Bottom Layer w6: v2(1070,2965) 1070,2800 1945,1925 1945,1367.17 2275.2,1036.97 2275.2,865 2327.2,813 2477,813 2487,803 2487,635 2437,585 2360,585 2315.5,540.5 2290.5,540.5 2274.71,524.71 J1.118@2274.71,461.79
B_SIMO: J1.122 J2.122 U24.11 | length 3411.2
  Top Layer w6: v1(2225,850) 2300,775 2300,680 2310,670 2310,575 v1(2303,568)
  Top Layer w8: U24.11@955,3270 955,3220 v2(985,3190)
  Bottom Layer w6: v2(985,3190) 1020,3155 1020,2830 1930,1920 1930,1365.2 2225.2,1070 J2.122@2225.2,920 ; J1.122@2224.71,461.79 J1.122@2224.71,485.6 ; J1.122@2224.71,485 2225.31,485.6 2225.31,500 2269.95,544.64 2293.31,568 v1(2303,568) ; v1(2225,850) J2.122@2225,920
B_SOMI: J1.124 J2.124 U22.12 | length 1814.4
  Top Layer w10: U22.12@1700,1945 v2(1770,1945)
  MidLayer2 w6: v1(2215,820) 2300,735 2300,605 v1(2285,590)
  Bottom Layer w6: v2(1770,1945) 1910,1805 1910,1325.2 2200.2,1035 J2.124@2200.2,914.96 ; J1.124@2199.71,461.79 2199.71,499.71 2285,585 v1(2285,590) ; J2.124@2200,910 2200,830 v1@2215,815
CDAT0: U9.E6 U11.59 | length 3234.7
  Top Layer w6: v3(2807.17,1877.2) U9.E6@2826.85,1857.52 ; U11.59@4037.09,4003.72 4037.09,4102.09 v1(4050,4115)
  MidLayer2 w6: v3(2807.17,1877.2) 2787.48,1896.89 2787.48,2037.52 2782,2043 2782,2997.79 3084.21,3300 3325,3300 3510,3485 3755,3485 3759.06,3489.06 3800,3530 3800,3920 3995,4115 v1(4050,4115)
CDAT1: U9.A5 U11.60 | length 2947.1
  Top Layer w6: U9.A5@2787.48,2015 2787.48,2142.48 v1(2820,2175) ; v1(4015,4090) 4017.4,4087.6 U11.60@4017.4,4003.72
  MidLayer2 w6: v1(2820,2175) 2820,3001.85 3088.15,3270 3465,3270 3666,3471 3761,3471 3815,3525 3815,3890 v1(4015,4090)
CDAT2: U9.B5 U11.61 | length 2926
  Top Layer w6: U9.B5@2787.48,1975.63 2807.17,1995.32 2807.17,2132.17 2850,2175 v1(2860,2175) ; U11.61@3997.72,4003.72 3997.72,3937.28 v1(4030,3905)
  MidLayer2 w6: v1(2860,2175) 2870,2185 2870,3034.88 3091.12,3256 3470.8,3256 3671.8,3457 3767,3457 3845,3535 3845,3835 3919.59,3909.59 3937.3,3927.3 4007.7,3927.3 v1(4030,3905)
CDAT3: U9.D6 U11.62 | length 2958.5
  Top Layer w6: v3(2807.17,1916.57) U9.D6@2826.85,1896.89 ; U11.62@3978.03,4003.72 3978.03,3916.97 v1(3995,3900)
  MidLayer2 w6: v3(2807.17,1916.57) 2826.85,1936.26 2826.85,2054.52 2912.33,2140 2912.33,2341.67 2884,2370 2884,3031.91 3092.09,3240 3475,3240 3670,3435 3775,3435 3870,3530 3870,3835 3935,3900 v1(3995,3900)
CDAT4: U9.A4 U11.63 | length 2761
  Top Layer w6: v1(2730,2045) 2750,2025 U9.A4@2750,2015 ; U11.63@3958.35,4003.72 3958.35,3881.65 v1(3960,3880)
  Bottom Layer w6: v1(2730,2045) 2766.35,2081.35 2766.35,2919.66 3104.2,3257.51 3306.6,3257.51 3528.09,3479 3759,3479 3905,3625 3905,3825 v1(3960,3880)
CDAT5: U9.B4 U11.86 | length 2392.9
  Top Layer w6: v1(2735,2085) 2735,2082.8 2767.8,2050 2767.8,1995.32 U9.B4@2748.11,1975.63 ; v1(3740,3570) 3764.96,3570 3800,3534.96 U11.86@3874.45,3534.96 ; U11.86@3874.45,3535 U11.86@3885,3535
  Bottom Layer w6: v1(2735,2085) 2746.96,2096.96 2752.35,2102.35 2752.35,2925.46 3098.4,3271.51 3300.8,3271.51 3542.34,3513.05 3543.05,3513.05 3585,3555 3725,3555 v1(3740,3570)
CDAT6: U9.A2 U11.87 | length 2376.6
  Top Layer w6: U9.A2@2669.37,2015 2669.37,2089.37 v1(2730,2150) ; v1(3755,3540) 3779.72,3515.28 U11.87@3874.45,3515.28
  MidLayer2 w6: v1(2730,2150) 2750,2170 2750,2999.74 3080.26,3330 3295,3330 3505,3540 v1(3755,3540)
CDAT7: U9.D5 U11.88 | length 2451.8
  Top Layer w6: v3(2767.8,1916.57) U9.D5@2787.48,1896.89 ; v1(3740,3510) 3754.41,3495.59 3865,3495.59 U11.88@3874.45,3495.59
  MidLayer2 w6: v3(2767.8,1916.57) 2748.11,1936.26 2748.11,2028.11 2770,2050 2770,3002.76 3082.24,3315 3305,3315 3500,3510 v1(3740,3510)
CLK_0N: J1.5 J2.5 U13.30 | length 1132.6
  Top Layer w6: v1(3775,1305) 3780,1300 U13.30@3780,1265 ; U13.30@3780.47,1262.52 U13.30@3780.47,1265 ; v1(4055,580) 4055,585 4055.21,584.79 J1.5@4055.21,462.85
  MidLayer2 w6: v1(3775,1305) 3805,1305 4106,1004 4106,656 4055,605 v1(4055,580)
  Bottom Layer w6: v1(4055,580) J2.5@4055,640
CLK_0P: J1.3 J2.3 U13.31 | length 1234.9
  Top Layer w6: v1(3730,1325) 3730,1315 3760,1285 U13.31@3760,1265 ; U13.31@3760.79,1262.52 U13.31@3760.79,1265 ; J1.3@4080,465 v1(4080,595)
  MidLayer2 w6: v1(3730,1325) 3735,1330 3815,1330 4120,1025 4120,635 v1(4080,595)
  Bottom Layer w6: v1(4080,595) 4080,659.33 J2.3@4080.51,659.84
CLK_1N: J1.6 J2.6 U13.28 | length 1413.9
  Top Layer w6: U13.28@3819.84,1262.52 3819.84,1290 ; 3820,1290 3820,1345 v1(3825,1350)
  Bottom Layer w6: v1(3825,1350) 3835,1360 3980.2,1360 4105,1235.2 4105,1020 4055,970 4055,900.51 J2.6@4055.51,900 ; J1.6@4055.21,462.85 4055,463.05 4055,505 4074,524 4120,524 4201,605 4201,804.2 4162.48,842.72 4082.28,842.72 4055.51,869.49 J2.6@4055.51,900.51
CLK_1P: J1.4 J2.4 U13.29 | length 1471.5
  Top Layer w6: v1(3790,1355) 3800.16,1344.84 U13.29@3800.16,1262.52
  Bottom Layer w6: v1(3790,1355) 3810,1375 3990,1375 4125,1240 4125,1015 4080,970 4080,865 4088.28,856.72 4168.28,856.72 4215,810 4215,595 4130,510 4095,510 4080.21,495.21 J1.4@4080.21,462.85 ; J2.4@4080,914.45 J2.4@4080.51,914.96
CLK_2N: J1.9 J2.9 U13.26 | length 1344.9
  Top Layer w6: U13.26@3859.21,1262.52 3859.21,1294.21 v1(3890,1325) ; v1(4005,535) 4005,463.05 J1.9@4005.21,462.85
  MidLayer2 w6: v1(3890,1325) 4200,1015 4200,605 4178.47,583.47 4130,535 v1(4005,535)
  Bottom Layer w6: v1(4005,535) 4005,659.33 J2.9@4005.51,659.84
CLK_2P: J1.7 J2.7 U13.27 | length 1313.6
  Top Layer w6: U13.27@3839.53,1262.52 3839.53,1319.53 v1(3855,1335) ; v1(4030,555) 4030.21,554.79 J1.7@4030.21,462.85
  MidLayer2 w6: v1(3855,1335) 3855,1325 4186,994 4186,616 4125,555 v1(4030,555)
  Bottom Layer w6: v1(4030,555) 4030,659.33 J2.7@4030.51,659.84
CLK_3N: J1.10 J2.10 U13.23 | length 1074.4
  Top Layer w6: U13.23@3902.52,1219.21 3930.79,1219.21 4018.89,1131.11 4045,1105 v1(4045,1030)
  Bottom Layer w6: J1.10@4005.21,462.85 4005,463.05 4005,500 4057,552 4100,552 4173,625 4173,792.6 4150.88,814.72 4045.28,814.72 4005.51,854.49 4005.51,990.51 v1(4045,1030)
CLK_3P: J1.8 J2.8 U13.24 | length 1082.3
  Top Layer w6: U13.24@3902.52,1238.9 3931.1,1238.9 3995.74,1174.26 4065,1105 v1(4065,1010)
  Bottom Layer w6: J1.8@4030.21,462.85 4030,463.05 4030,500 4068,538 4110,538 4187,615 4187,798.4 4156.68,828.72 4066.28,828.72 4030,865 4030,975 v1(4065,1010)
CLK_4N: J1.15 J2.15 U13.21 | length 931.6
  Top Layer w6: U13.21@3902.52,1179.84 3920.36,1179.84 3997,1103.2 3997,752 v1(3995,750) 3995,585 3987.61,577.61 3987.61,577.2 3930.21,519.8 J1.15@3930.21,462.85
  Bottom Layer w6: J2.15@3930.51,659.84 3930.51,715.51 3938.81,723.81 ; 3938.81,723.81 3944.79,729.79 3979.79,729.79 3995,745 v1(3995,750)
CLK_4P: J1.13 J2.13 U13.22 | length 971.7
  Top Layer w6: U13.22@3902.52,1199.53 3920.47,1199.53 4011,1109 4011,773.88 v1(4029.88,755) 4029.88,599.67 3955.21,525 J1.13@3955.21,462.85
  Bottom Layer w6: J2.13@3955.51,659.84 3955.51,705.51 3965.79,715.79 3990.91,715.79 4030,754.88 v1(4029.88,755)
CLK_5N: J1.19 J2.19 U13.19 | length 897.1
  Top Layer w6: J1.19@3880,465 3880,509.19 3946.96,576.15 3960,589.19 3960,714.59 v1(3917.29,757.29) 3969,809 3969,1091.6 3920.13,1140.47 U13.19@3902.52,1140.47
  Bottom Layer w6: J2.19@3880,665 3880,720 v1@3920,760
CLK_5P: J1.17 J2.17 U13.20 | length 911.3
  Top Layer w6: U13.20@3902.52,1160.16 3920.24,1160.16 3983,1097.4 3983,783 v1(3955,755) 3975,735 3975,584.39 3956.23,565.62 3905.21,514.6 J1.17@3905.21,462.85
  Bottom Layer w6: J2.17@3905.51,659.84 3905.51,715.51 3945,755 v1(3955,755)
CLK_6N: J1.16 J2.16 U13.17 | length 774
  Top Layer w6: U13.17@3902.52,1101.1 3917.1,1101.1 3941,1077.2 3941,861 v1(3930,850) 3930,830 3880,780 3880,610 v1(3910,580)
  Bottom Layer w6: v1(3910,580) 3930.21,559.79 J1.16@3930.21,462.85 ; v1(3930,850) 3930,914.45 J2.16@3930.51,914.96
CLK_6P: J1.14 J2.14 U13.18 | length 851.2
  Top Layer w6: U13.18@3902.52,1120.79 3917.21,1120.79 3955,1083 3955,825 3894,764 3894,637.01 v1(3935,596.01)
  Bottom Layer w6: v1(3935,596.01) 3935,600 3955.21,579.79 J1.14@3955.21,462.85 ; v1@3945,815 3955.51,825.51 J2.14@3955.51,914.96
  other v1: 3947.13,817.13
CLK_7N: J1.26 J2.26 U13.14 | length 741.1
  Top Layer w6: v1(3805.21,559.79) 3805.21,574.79 3765,615 3765,810 3856,901 3856,1029 3839.53,1045.47 U13.14@3839.53,1077.48
  Bottom Layer w6: v1@3805,559.59 v1(3805.21,559.79) J1.26@3805.21,462.85 ; v1(3805,850) J2.26@3805,914.96
CLK_7P: J1.24 J2.24 U13.15 | length 784.3
  Top Layer w6: v1(3820,590) 3779,631 3779,789 v1(3810,820) 3810,825 3870,885 3870,1040 3859.21,1050.79 U13.15@3859.21,1077.48
  Bottom Layer w6: v1(3810,820) 3815,820 3830,835 3830,914.45 J2.24@3830.51,914.96 ; v1(3820,590) 3830,580 3830,550 ; J1.24@3830.21,462.85 3830.21,550
CLK_8N: J1.25 J2.25 U13.12 | length 752.1
  Top Layer w6: U13.12@3800,1075 3800,1020 v1(3805,1015) ; v1(3805,720) 3845,680 3845,565 3805.21,525.21 J1.25@3805.21,462.85
  MidLayer2 w6: v1(3805,720) 3763,762 3763,973 v1(3805,1015)
  Bottom Layer w6: J2.25@3805,650 v1(3805,720)
CLK_8P: J1.23 J2.23 U13.13 | length 776.3
  Top Layer w6: U13.13@3819.84,1077.48 3819.84,1029.86 3835,1014.7 v1(3835,1010) ; J1.23@3830,470 3830,530.2 3859,559.2 3859,716 v1(3830,745) ; J1.23@3830.21,462.85 J1.23@3830.21,470
  MidLayer2 w6: v1(3830,745) 3777,798 3777,952 v1(3835,1010)
  Bottom Layer w6: v1(3830,745) 3830.51,744.49 J2.23@3830.51,659.84
CLK_9N: J1.20 J2.20 U13.10 | length 745.8
  Top Layer w6: v1(3745,1035) 3760.79,1050.79 U13.10@3760.79,1077.48
  MidLayer2 w6: v1@3870,840 3855,825 3855,565 v1(3875,545)
  Bottom Layer w6: v1(3745,1035) 3745,1020 3790,975 3875,975 3880.51,969.49 J2.20@3880.51,940 ; v1@3870,840 3880,850 J2.20@3880,940 ; v1@3880,545 3880.21,544.79 J1.20@3880.21,462.85
  other v1: 3875,845
CLK_9P: J1.18 J2.18 U13.11 | length 756.1
  Top Layer w6: v1(3775,1025) 3780.47,1030.47 U13.11@3780.47,1077.48 ; U13.11@3780,1077.48 U13.11@3780,1080
  MidLayer2 w6: v1(3885,570) 3869,586 3869,799 v1(3890,820)
  Bottom Layer w6: v1(3775,1025) 3775,1009.8 3795.8,989 3886,989 3905.51,969.49 J2.18@3905.51,880 ; v1(3885,570) 3905,550 3905,520 ; v1(3890,820) 3905,835 J2.18@3905,880 ; J1.18@3905.21,462.85 3905.21,520
CLK_24_OUT: R43.1 U9.A10 | length 204.4
  Top Layer w6: U9.A10@2984.33,2015 2984.33,2154.33 2995,2165 R43.1@2995,2214.99
CLK_24MSP: R5.2 U29.89 | length 934.9
  Top Layer w6: v1(4935,2185) 4937.44,2187.44 U29.89@5001.02,2187.44
  Top Layer w8: R5.2@4939.99,2880 4970,2880 v2(5015,2835)
  Bottom Layer w6: v1(4935,2185) 4935,2190 5125,2380 5125,2720 5015,2830 v2(5015,2835)
CLK_48_M: R22.2 U9.B9 | length 2545.3
  Top Layer w6: U9.B9@2944.96,1975.63 v3(2964.65,1995.32) ; v1(4490,3105) 4535,3150 4740,3150 4760,3170 R22.2@4760,3204.99
  Bottom Layer w6: v3(2964.65,1995.32) 2989.28,2019.95 2989.28,2115 2990,2115.72 2990,2360 3737.11,3107.11 4487.89,3107.11 v1(4490,3105)
CLK_100: R16.2 U9.T8 | length 1436.4
  Top Layer w6: U9.T8@2905.59,1424.45 2905.59,1419.69 2899.91,1414 2899.91,1365.09 v1(2910,1355) ; v1(3980,1605) 3989.99,1614.99 R16.2@4155,1614.99
  MidLayer1 w6: v1(2910,1355) 2919.29,1345.71 3455.71,1345.71 3680,1570 3945,1570 v1(3980,1605)
CLK_100_A: R12.2 U9.M15 | length 1133
  Top Layer w6: U9.M15@3181.18,1581.93 3200.87,1562.24 3277.76,1562.24 3335,1505 3470,1505 3535,1570 3860,1570 3871.03,1581.03 4211.03,1581.03 4225,1595 R12.2@4225,1614.99
CONF_DONE: J3.3 RN1.2 U9.H14 U11.78 | length 5985.2
  Top Layer w6: RN1.2@2290.01,1855 v1(2330,1855) ; U9.H14@3141.81,1739.41 3161.5,1759.09 v3(3161.5,1798.46) ; U11.78@3874.45,3692.44 3992.56,3692.44 4030,3655 v1(4140,3655)
  Top Layer w8: v2(5400,1920) 5475,1995 5595,1995 J3.3@5600,2000
  MidLayer1 w6: v3(3161.5,1798.46) 3163.46,1798.46 3185,1820 3335,1820 v1(3345,1830)
  MidLayer2 w6: v1(3345,1830) 3420,1905 3420,2270 3465,2315 3465,2650 3815.2,3000.2 3815.2,3102.32 4117,3404.12 4117,3632 v1(4140,3655)
  MidLayer3 w6: v1(2330,1855) 2406.22,1778.78 2630,1778.78 2669.37,1818.15 3141.81,1818.15 v3(3161.5,1798.46) ; v1(3345,1830) 3385,1870 4058.03,1870 4098.03,1910 4455,1910 4470.63,1894.37 4495,1870 5350,1870 v2(5400,1920)
CONVST: J1.29 J2.29 U9.J16 | length 1641.4
  Top Layer w6: U9.J16@3220.55,1700.04 3240.24,1719.72 v1(3279.61,1719.72) ; J1.29@3755,465 3755,525 3780,550 3780,570 v1(3760,590)
  MidLayer2 w6: v1(3279.61,1719.72) 3330.28,1719.72 3590,1460 3590,1149 3709.93,1029.07 3749,990 3749,601 v1(3760,590)
  Bottom Layer w6: J2.29@3755.51,659.84 3755,659.33 3755,600 3760,595 v1(3760,590)
DAC_CS_N: U4.1 U29.68 | length 1385.2
  Top Layer w6: v1(4800,1750) 4802.2,1752.2 U29.68@4802.2,1870.51 ; v1(5210,725) 5210,730 5210.55,729.45 U4.1@5210.55,695.59
  Bottom Layer w8: v1(4800,1750) 4800,1085 5160,725 v1(5210,725)
DATA: C46.1 D4.1 J3.7 R2.2 U9.H2 | length 4572.5
  Top Layer w6: v1(2210,2125) 2215,2120 D4.1@2215,2080 2215,2055 2225.01,2044.99 2250.01,2044.99 2285,2010 C46.1@2285,1990.01 ; C46.1@2290,1990 2370,1990 2485,1875 2485,1835 2472.02,1822.02 2472.02,1777.98 2490.91,1759.09 2649.68,1759.09 U9.H2@2669.37,1739.41 ; v1(4190,2380) 4225,2415 R2.2@4245.01,2415
  MidLayer1 w6: v1(2210,2125) 2215,2130 2295,2130 2410,2245 3385,2245 3462,2322 3478.97,2322 4132,2322 v1(4190,2380)
  MidLayer3 w6: v1(4190,2380) 4350,2380 4440,2290 4885,2290 5040,2135 5320,2135 5535,1920 5535,1855 J3.7@5590,1800
DC_HOLD: J1.47 J2.47 U9.J13 | length 1577.3
  Top Layer w6: U9.J13@3102.44,1700.04 v3(3122.13,1719.72) ; v1(3495,730) 3520,705 3520,510 3530,500 J1.47@3530,462.85
  MidLayer2 w6: v3(3122.13,1719.72) 3122.13,1717.87 3226.69,1613.31 3226.69,998.31 3285,940 3335,940 3495,780 v1(3495,730)
  Bottom Layer w6: v1(3495,730) 3510,730 3530.51,709.49 J2.47@3530.51,659.84 J2.47@3530,660.35
DCLK: C21.1 D3.2 J3.1 U1.6 U9.H1 | length 4829.1
  Top Layer w6: D3.2@2365,1685.2 2389.8,1685.2 v1(2406.08,1668.92) 2420,1655 C21.1@2420,1635 ; C21.1@2420,1625.01 2435.01,1625.01 2480,1670 2480,1720 2499.41,1739.41 U9.H1@2630,1739.41 ; v1(3775,2505) 3775,2445 3820,2400 U1.6@3895,2400
  MidLayer3 w6: v1(2315,2385) 2380,2450 2780,2450 2835,2505 v1(3775,2505) 3790,2490 4120,2490 4185,2425 4338.94,2425 4443.94,2320 4902,2320 5063,2159 5360,2159 5419,2100 J3.1@5600,2100
  Bottom Layer w6: v1(2315,2385) 2315,2380 2332,2363 2332,1967.09 2406.08,1893.01 v1(2406.08,1668.92)
DRV_1_SEL_N: J1.99 J2.99 U29.58 | length 3089.5
  Top Layer w6: v1(2640,750) 2649,741 2649,551 2689.86,510.14 J1.99@2689.86,461.79 ; v1(4520,1535) 4528.33,1543.33 4528.33,1710.4 4543.36,1725.44 4605.35,1787.43 U29.58@4605.35,1870.51
  MidLayer1 w6: v1(2640,750) 2640,870 2818,1048 3621.66,1048 3678.4,1104.75 4114.75,1104.75 v1(4150,1140)
  Bottom Layer w6: v1(2640,750) 2650,750 2690,710 J2.99@2690,670 ; J2.99@2690.35,659.84 J2.99@2690.35,670
  Bottom Layer w8: v1(4150,1140) 4155,1140 4520,1505 v1(4520,1535)
DRV_2_SEL_N: J1.100 J2.100 U29.59 | length 3399.8
  Top Layer w6: v1(4570,1705) 4569.07,1705.93 4569.07,1734.18 4625.04,1790.15 U29.59@4625.04,1870.51
  MidLayer1 w6: v1(2650,1055) 2699,1104 3598.46,1104 3641.45,1146.99 3655.21,1160.75 4027.64,1160.75 4086.9,1220 4445,1220 v1(4455,1230)
  Bottom Layer w6: v1(2650,1055) 2645.52,1050.52 2645.52,1009.48 2690,965 J2.100@2690,915 ; J1.100@2689.86,461.79 2689.86,520.14 2658,552 2625,552 2557,620 2557,822.2 2580,845.2 2670.2,845.2 2690,865 2690,914.61 J2.100@2690.35,914.96
  Bottom Layer w8: v1(4455,1230) 4475,1230 4550,1305 4550,1690 4565,1705 v1(4570,1705)
DRV_3_SEL_N: J1.101 J2.101 U29.60 | length 3300.1
  Top Layer w6: v1(2615,730) 2635,710 2635,534.86 2664.86,505 J1.101@2664.86,461.79 ; v1(4610,1700) 4612.32,1702.32 4612.32,1760.45 4644.72,1792.86 U29.60@4644.72,1870.51
  MidLayer1 w6: v1(2615,730) 2615,865 2812,1062 3615.86,1062 3633.35,1079.5 3672.6,1118.75 4036.56,1118.75 4097.81,1180 4485,1180 v1(4490,1175)
  Bottom Layer w6: v1(2615,730) 2620,725 2650,725 2665.35,709.65 J2.101@2665.35,659.84 J2.101@2665,660.2
  Bottom Layer w8: v1(4490,1175) 4610,1295 v1(4610,1700)
DRV_4_SEL_N: J1.102 J2.102 U29.61 | length 3377.3
  Top Layer w6: v1(4640,1745) 4664.41,1769.41 U29.61@4664.41,1870.51
  MidLayer3 w6: v1(2600,1265) 2640,1305 3585,1305 3675,1395 4075,1395 4418.88,1738.88 4425,1745 v1(4640,1745)
  Bottom Layer w6: v1@2600,1270 v1(2600,1265) 2620,1245 2620,1000 2665.35,954.65 J2.102@2665.35,920 ; J1.102@2664.86,461.79 2664.86,520.14 2647,538 2615,538 2543,610 2543,833 2570,860 2660,860 2665.35,865.35 J2.102@2665.35,914.96
FIFO_RESET_N: U9.M16 U11.72 U15.62 U16.62 U18.62 U19.62 | length 6562.7
  Top Layer w6: U15.62@1647.48,4093 1647.48,3997.52 v2(1650,3995) ; v2(1655,3065) 1657.48,3067.48 U16.62@1657.48,3143 ; U19.62@2755,3150 2755,3080 2850,2985 v1(3075,2985) ; U19.62@2757.48,3143 2757.48,3217.48 v1(2760,3220) ; U18.62@2757.48,4093 2757.48,3752.52 v1(2760,3750) ; U9.M16@3220.55,1581.93 3293.07,1581.93 v1(3325,1550) ; v1(3755,3720) 3755,3750 3815.55,3810.55 U11.72@3874.45,3810.55
  MidLayer1 w6: v2(1655,3065) 1775,3185 2725,3185 v1(2760,3220) ; v1(2760,3750) 2760,3745 2785,3720 v1(3755,3720)
  MidLayer2 w6: v2(1650,3995) 1690,3955 1690,3095 1660,3065 v2(1655,3065) ; v1(3075,2985) 3062.8,2972.8 3062.8,2829.17 3183,2708.97 3183,2440.03 3232.55,2390.48 3232.55,1889.2 3220.55,1877.2 3220.55,1739.49 3260,1700.04 3275,1700.04 3325,1650.04 v1(3325,1550)
  Bottom Layer w6: v1(2760,3220) v1(2760,3750)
